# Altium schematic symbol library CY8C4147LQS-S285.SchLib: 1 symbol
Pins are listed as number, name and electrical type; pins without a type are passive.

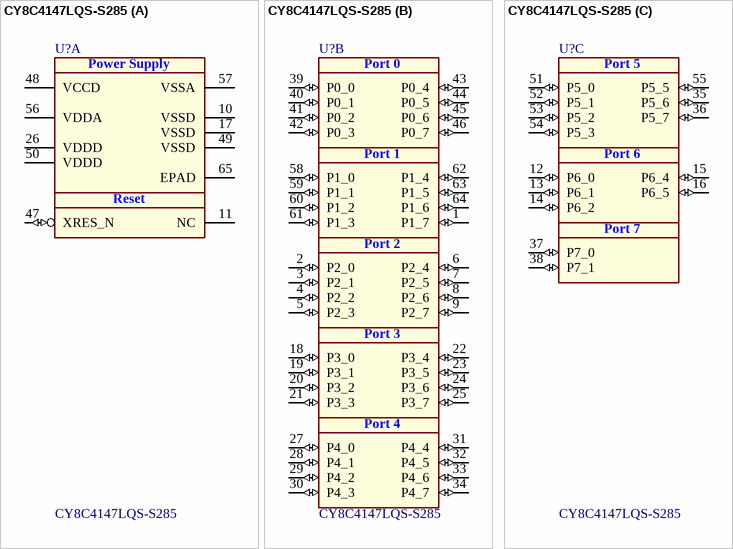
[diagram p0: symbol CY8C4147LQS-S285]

## CY8C4147LQS-S285
designator U?
Programmable System-on-Chip (PSoC); Manufacturer: Infineon Technologies
part A pins: 10 VSSD (power) "Ground pins for the digital section", 11 NC "Not Connected", 17 VSSD (power) "Ground pins for the digital section", 26 VDDD (power) "Power supply for the digital section", 47 XRES_N (io) "External reset I/O pin", 48 VCCD (power) "Regulated digital supply (1.8 V ±5%)", 49 VSSD (power) "Ground pins for the digital section", 50 VDDD (power) "Power supply for the digital section", 56 VDDA (power) "Power supply for the analog section", 57 VSSA (power) "Ground pins for the analog section", 65 EPAD (power) "Exposed Pad"
part B pins: 1 P1_7 (io) "I/O Pin", 2 P2_0 (io) "I/O Pin", 3 P2_1 (io) "I/O Pin", 4 P2_2 (io) "I/O Pin", 5 P2_3 (io) "I/O Pin", 6 P2_4 (io) "I/O Pin", 7 P2_5 (io) "I/O Pin", 8 P2_6 (io) "I/O Pin", 9 P2_7 (io) "I/O Pin", 18 P3_0 (io) "I/O Pin", 19 P3_1 (io) "I/O Pin", 20 P3_2 (io) "I/O Pin", 21 P3_3 (io) "I/O Pin", 22 P3_4 (io) "I/O Pin", 23 P3_5 (io) "I/O Pin", 24 P3_6 (io) "I/O Pin", 25 P3_7 (io) "I/O Pin", 27 P4_0 (io) "I/O Pin", 28 P4_1 (io) "I/O Pin", 29 P4_2 (io) "I/O Pin", 30 P4_3 (io) "I/O Pin", 31 P4_4 (io) "I/O Pin", 32 P4_5 (io) "I/O Pin", 33 P4_6 (io) "I/O Pin", 34 P4_7 (io) "I/O Pin", 39 P0_0 (io) "I/O Pin", 40 P0_1 (io) "I/O Pin", 41 P0_2 (io) "I/O Pin", 42 P0_3 (io) "I/O Pin", 43 P0_4 (io) "I/O Pin", 44 P0_5 (io) "I/O Pin", 45 P0_6 (io) "I/O Pin", 46 P0_7 (io) "I/O Pin", 58 P1_0 (io) "I/O Pin", 59 P1_1 (io) "I/O Pin", 60 P1_2 (io) "I/O Pin", 61 P1_3 (io) "I/O Pin", 62 P1_4 (io) "I/O Pin", 63 P1_5 (io) "I/O Pin", 64 P1_6 (io) "I/O Pin"
part C pins: 12 P6_0 (io) "I/O Pin", 13 P6_1 (io) "I/O Pin", 14 P6_2 (io) "I/O Pin", 15 P6_4 (io) "I/O Pin", 16 P6_5 (io) "I/O Pin", 35 P5_6 (io) "I/O Pin", 36 P5_7 (io) "I/O Pin", 37 P7_0 (io) "I/O Pin", 38 P7_1 (io) "I/O Pin", 51 P5_0 (io) "I/O Pin", 52 P5_1 (io) "I/O Pin", 53 P5_2 (io) "I/O Pin", 54 P5_3 (io) "I/O Pin", 55 P5_5 (io) "I/O Pin"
